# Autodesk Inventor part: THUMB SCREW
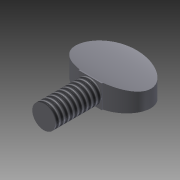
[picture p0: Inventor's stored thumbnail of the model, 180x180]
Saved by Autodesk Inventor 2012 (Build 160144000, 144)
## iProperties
Shininess: 64.0
Length Units: 11272
Angle Units: 11279
Time Units: 11290
Mass Units: 11286
Length Display Precision: 3
Angle Display Precision: 2
Compacted: True
Part Number: THUMB SCREW
Document SubType Name: Modeling
Created: 2003-11
Designer: Autodesk, Inc.
Manufacturer: Standard
Standards Organization: Custom
Mass: 11.3688 g
Surface Area: 9.71998 cm^2
Volume: 1.44641 cm^3
Density: 7.86 g/cm^3
Material: Steel, Mild
Density: 0.0
Volumn: 0.0
Area: 0.0
PropertySet Name: Model Information
Control State: 0
Master: False
Checked Out: False
Author: Autodesk, Inc.
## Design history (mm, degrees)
sketch "Sketch1"
  geometry: C1 r 3.175 at (0, 0); 1 further point
  constraints: 1 centre point, 1 coincident
  dimensions: "d0" = 6.35 diameter of C1
extrude "Extrusion1" new body sketch "Sketch1" distance "d1" = 12.7; taper "d2" = 0 deg
sketch "Sketch2"
  geometry: L1 (-10.312, 3.175)-(10.312, 3.175); L2 (10.312, 3.175)-(10.312, -3.175); L3 (10.312, -3.175)-(-10.312, -3.175); L4 (-10.312, -3.175)-(-10.312, 3.175); C1 r 3.175 at (0, 0) reference; 1 further point
  constraints: 8 end point, 2 parallel, 1 horizontal, 1 perpendicular
  dimensions: "d3" = 3.175 distance from line of L3 point (0, 0); "d4" = 3.175 distance from line of point (0, 0) L1; "d5" = 20.6248 distance between parallel lines of L2 L4; "d6" = 10.3124 distance from line of L4 point (0, 0) (= 0.5 x d5)
extrude "Extrusion2" join sketch "Sketch2" distance "d7" = 12.7; taper "d8" = 0 deg
sketch "Sketch3"
  geometry: L1 (20.625, 12.7)-(0, 12.7) reference; L2 (0, 0)-(0, 12.7) reference; L3 (10.312, 0)-(0, 0) reference; L4 (20.625, 0)-(10.312, 0) reference; L5 (20.625, 0)-(20.625, 12.7) reference; L6 (10.312, 12.7)-(10.312, 0); L7 (0, 6.35)-(20.625, 6.35); L8 (7.137, 0)-(7.137, -12.7) reference; L9 (13.487, 0)-(13.487, -12.7) reference; L10 (7.137, 0)-(7.137, 0.308); L11 (13.487, 0)-(13.487, 0.308); 1 further point; 1 other entity
  constraints: 8 end point, 4 midpoint, 3 vertical, 1 parallel, 6 other
extrude "Extrusion3" cut sketch "Sketch3" distance "d9" = 12.7; taper "d10" = 0 deg
workplane "Work Plane1"
sketch "Sketch4"
  geometry: L1 (-3.175, -0.308)-(-3.175, -0.308) reference; L2 (3.175, -0.308)-(-3.175, -0.308) reference; L3 (3.175, -0.308)-(3.175, -0.308) reference; L4 (3.175, -0.308)-(-3.175, -0.308) reference; L5 (-3.175, -0.308)-(-3.175, -12.7) reference; L6 (3.175, -12.7)-(3.175, -0.308) reference; L7 (3.175, -12.7)-(3.175, -0.308); L8 (-3.175, -0.308)-(-3.175, -12.7); A1 r 22.382 centre (-24.682, -6.504) between (-3.175, -12.7) and (-3.175, -0.308); A2 r 22.382 centre (24.682, -6.504) between (3.175, -0.308) and (3.175, -12.7)
  constraints: 4 end point, 4 point on circle, 2 centre point, 2 equal length
  dimensions: "d12" = 22.38154 radius of A1; "d13" = 22.38154 radius of A2 (= d12)
extrude "Extrusion4" cut sketch "Sketch4" distance "d14" = 25.4; taper "d15" = 0 deg
thread "Thread1" dims "d16" = 25.4, "d17" = 0
body "Solid1"
node "Projected Loop1"
node "Projected Loop2"
other parameters: "d11" = -12.7
